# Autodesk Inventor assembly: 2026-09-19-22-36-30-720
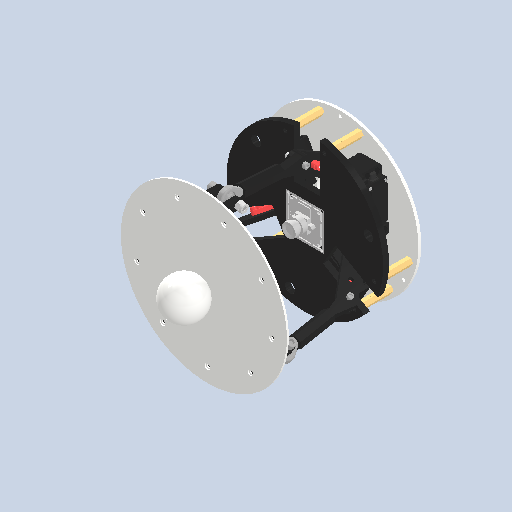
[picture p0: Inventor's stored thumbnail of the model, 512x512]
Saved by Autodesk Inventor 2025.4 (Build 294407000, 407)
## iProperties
Created: 2026-09
Part Number: 2026-09-19-22-36-30-720
Document SubType Name: Assembly
Designer: AdminForWorker
Title: ENSAMBLE_PLATO v7
Author: AdminForWorker
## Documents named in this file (29)
- c:\worker\convert-fusion-r05-cosv3\tmp\job-1\19\temp\files\ca3d996b-dda0-445d-8bee-12a194174ca8\770bcd22-a618-4276-8335-3e11de9b40c0.iam
- c:\worker\convert-fusion-r05-cosv3\tmp\job-1\19\temp\files\ca3d996b-dda0-445d-8bee-12a194174ca8\MG995 v1.iam
- c:\worker\convert-fusion-r05-cosv3\tmp\job-1\19\temp\files\ca3d996b-dda0-445d-8bee-12a194174ca8\Base v9 v2.ipt
- c:\worker\convert-fusion-r05-cosv3\tmp\job-1\19\temp\files\ca3d996b-dda0-445d-8bee-12a194174ca8\MG995 v1_1.iam
- c:\worker\convert-fusion-r05-cosv3\tmp\job-1\19\temp\files\ca3d996b-dda0-445d-8bee-12a194174ca8\MG995 v1_2.iam
- c:\worker\convert-fusion-r05-cosv3\tmp\job-1\19\temp\files\ca3d996b-dda0-445d-8bee-12a194174ca8\SERVO ARM HORN 25T ALUMINIUM v1.ipt
- c:\worker\convert-fusion-r05-cosv3\tmp\job-1\19\temp\files\ca3d996b-dda0-445d-8bee-12a194174ca8\Link2 v9 v1.ipt
- c:\worker\convert-fusion-r05-cosv3\tmp\job-1\19\temp\files\ca3d996b-dda0-445d-8bee-12a194174ca8\MR104_ball_bearing v1.ipt
- c:\worker\convert-fusion-r05-cosv3\tmp\job-1\19\temp\files\ca3d996b-dda0-445d-8bee-12a194174ca8\Link1 v7 v1.ipt
- c:\worker\convert-fusion-r05-cosv3\tmp\job-1\19\temp\files\ca3d996b-dda0-445d-8bee-12a194174ca8\Arducam B0332 v1.ipt
- c:\worker\convert-fusion-r05-cosv3\tmp\job-1\19\temp\files\ca3d996b-dda0-445d-8bee-12a194174ca8\top_ring v2 v1.ipt
- c:\worker\convert-fusion-r05-cosv3\tmp\job-1\19\temp\files\ca3d996b-dda0-445d-8bee-12a194174ca8\Tornillo de cabeza hexagonal hueca ISO 4762 - M5 x 30 Acero 4.6 Normal v1.ipt
- c:\worker\convert-fusion-r05-cosv3\tmp\job-1\19\temp\files\ca3d996b-dda0-445d-8bee-12a194174ca8\rotula v1.iam
- c:\worker\convert-fusion-r05-cosv3\tmp\job-1\19\temp\files\ca3d996b-dda0-445d-8bee-12a194174ca8\rotula v1_1.iam
- c:\worker\convert-fusion-r05-cosv3\tmp\job-1\19\temp\files\ca3d996b-dda0-445d-8bee-12a194174ca8\rotula v1_2.iam
- c:\worker\convert-fusion-r05-cosv3\tmp\job-1\19\temp\files\ca3d996b-dda0-445d-8bee-12a194174ca8\top_panel v5 v2.ipt
- c:\worker\convert-fusion-r05-cosv3\tmp\job-1\19\temp\files\ca3d996b-dda0-445d-8bee-12a194174ca8\mediomod v1.ipt
- c:\worker\convert-fusion-r05-cosv3\tmp\job-1\19\temp\files\ca3d996b-dda0-445d-8bee-12a194174ca8\stanofff v1.iam
- c:\worker\convert-fusion-r05-cosv3\tmp\job-1\19\temp\files\ca3d996b-dda0-445d-8bee-12a194174ca8\stanofff v1_1.iam
- c:\worker\convert-fusion-r05-cosv3\tmp\job-1\19\temp\files\ca3d996b-dda0-445d-8bee-12a194174ca8\stanofff v1_2.iam
- c:\worker\convert-fusion-r05-cosv3\tmp\job-1\19\temp\files\ca3d996b-dda0-445d-8bee-12a194174ca8\stanofff v1_3.iam
- c:\worker\convert-fusion-r05-cosv3\tmp\job-1\19\temp\files\ca3d996b-dda0-445d-8bee-12a194174ca8\stanofff v1_4.iam
- c:\worker\convert-fusion-r05-cosv3\tmp\job-1\19\temp\files\ca3d996b-dda0-445d-8bee-12a194174ca8\stanofff v1_5.iam
- c:\worker\convert-fusion-r05-cosv3\tmp\job-1\19\temp\files\ca3d996b-dda0-445d-8bee-12a194174ca8\Tornillo de cabeza hexagonal hueca ISO 4762 - M3 x 15 Acero 4.6 Normal v1.ipt
- c:\worker\convert-fusion-r05-cosv3\tmp\job-1\19\temp\files\ca3d996b-dda0-445d-8bee-12a194174ca8\Tuerca autoblocante hexagonal normal ISO 7040 - M4 Acero 6 Normal v1.ipt
- c:\worker\convert-fusion-r05-cosv3\tmp\job-1\19\temp\files\ca3d996b-dda0-445d-8bee-12a194174ca8\Tuerca autoblocante hexagonal normal ISO 7040 - M5 Acero 6 Normal v1.ipt
- c:\worker\convert-fusion-r05-cosv3\tmp\job-1\19\temp\files\ca3d996b-dda0-445d-8bee-12a194174ca8\Arandela NF E25-514 - L3 Acero 100 HV Normal v1.ipt
- c:\worker\convert-fusion-r05-cosv3\tmp\job-1\19\temp\files\ca3d996b-dda0-445d-8bee-12a194174ca8\Tuerca autoblocante hexagonal normal ISO 7040 - M3 Acero 6 Normal v1.ipt
- c:\worker\convert-fusion-r05-cosv3\tmp\job-1\19\temp\files\ca3d996b-dda0-445d-8bee-12a194174ca8\bolita v1.ipt
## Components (48 placed, 19 different names)
1. MG995 v1:1 [sub-assembly]
2. Base v9 v2:1
3. MG995 v1:2 [sub-assembly]
4. MG995 v1:3 [sub-assembly]
5. SERVO ARM HORN 25T ALUMINIUM v1:1
6. SERVO ARM HORN 25T ALUMINIUM v1:2
7. SERVO ARM HORN 25T ALUMINIUM v1:3
8. Link2 v9 v1:1
9. Link2 v9 v1:2
10. Link2 v9 v1:3
11. MR104_ball_bearing v1:1
12. MR104_ball_bearing v1:2
13. MR104_ball_bearing v1:3
14. Link1 v7 v1:1
15. Link1 v7 v1:2
16. Link1 v7 v1:3
17. MR104_ball_bearing v1:4
18. MR104_ball_bearing v1:5
19. MR104_ball_bearing v1:6
20. Arducam B0332 v1:1
21. top_ring v2 v1:1
22. Tornillo de cabeza hexagonal hueca ISO 4762 - M5 x 30 Acero 4.6 Normal v1:1
23. Tornillo de cabeza hexagonal hueca ISO 4762 - M5 x 30 Acero 4.6 Normal v1:2
24. Tornillo de cabeza hexagonal hueca ISO 4762 - M5 x 30 Acero 4.6 Normal v1:3
25. rotula v1:1 [sub-assembly]
26. rotula v1:2 [sub-assembly]
27. rotula v1:3 [sub-assembly]
28. top_panel v5 v2:1
29. mediomod v1:1
30. stanofff v1:1 [sub-assembly]
31. stanofff v1:2 [sub-assembly]
32. stanofff v1:3 [sub-assembly]
33. stanofff v1:4 [sub-assembly]
34. stanofff v1:5 [sub-assembly]
35. stanofff v1:6 [sub-assembly]
36. Tornillo de cabeza hexagonal hueca ISO 4762 - M3 x 15 Acero 4.6 Normal v1:1
37. Tornillo de cabeza hexagonal hueca ISO 4762 - M3 x 15 Acero 4.6 Normal v1:2
38. Tornillo de cabeza hexagonal hueca ISO 4762 - M3 x 15 Acero 4.6 Normal v1:3
39. Tuerca autoblocante hexagonal normal ISO 7040 - M4 Acero 6 Normal v1:1
40. Tuerca autoblocante hexagonal normal ISO 7040 - M5 Acero 6 Normal v1:1
41. Tuerca autoblocante hexagonal normal ISO 7040 - M5 Acero 6 Normal v1:2
42. Arandela NF E25-514 - L3 Acero 100 HV Normal v1:1
43. Arandela NF E25-514 - L3 Acero 100 HV Normal v1:2
44. Arandela NF E25-514 - L3 Acero 100 HV Normal v1:3
45. Tuerca autoblocante hexagonal normal ISO 7040 - M3 Acero 6 Normal v1:1
46. Tuerca autoblocante hexagonal normal ISO 7040 - M3 Acero 6 Normal v1:2
47. Tuerca autoblocante hexagonal normal ISO 7040 - M3 Acero 6 Normal v1:3
48. bolita v1:1
